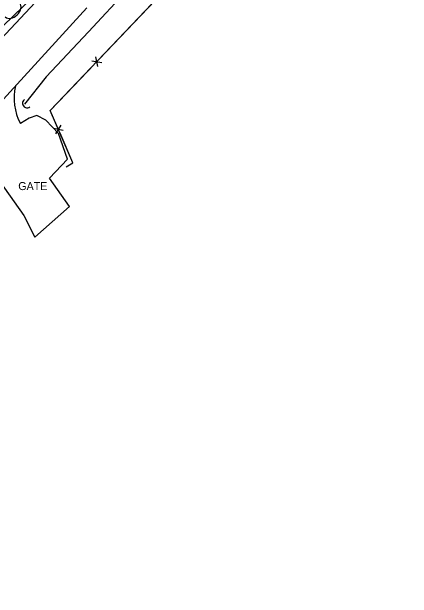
# Model space of a CAD drawing. Extents: x 978516 to 993312, y 1836504 to 1846212.
# Drawn here: x 991834.3 to 992034.4, y 1838414.8 to 1838707.8 of the extents above; entities that cross this region are included whole.
import ezdxf

# ---------------------------------------------------------------- set-up
doc = ezdxf.new("R2010")
doc.units = 0
for name, color, linetype in [('S_CROSS_DRAIN', 7, 'Continuous'), ('S_EDGE_PAVEMENT', 7, 'Continuous'), ('S_FENCE', 7, 'Continuous'), ('S_GATE_ANNOT', 7, 'Continuous'), ('S_PARKING', 7, 'Continuous'), ('S_STREAM', 7, 'Continuous'), ('S_TREE', 7, 'Continuous')]:
    doc.layers.add(name, color=color, linetype=linetype)

msp = doc.modelspace()

# ---------------------------------------------------------------- linework, layer by layer
at = {"layer": 'S_CROSS_DRAIN'}
msp.add_arc((991841.99, 1838662.1), 2.3, 126.4899, 306.8191, dxfattribs=at)
at = {"layer": 'S_EDGE_PAVEMENT'}
for points in [[(991619, 1838423.36), (991630.2, 1838441.16), (991653.43, 1838482.79), (991676.53, 1838520.74), (991692.11, 1838542.33), (991709.31, 1838562.78), (991757.84, 1838618.11), (991795.59, 1838658.21), (991828.79, 1838694.04), (991858.22, 1838725.78)], [(991871.79, 1838709.82), (991824.61, 1838658.29), (991793.15, 1838625.63), (991745.8, 1838573.38), (991714.08, 1838535.8), (991699.23, 1838517.15), (991680.52, 1838488.09), (991668.35, 1838467.09), (991649.18, 1838432.48), (991638.1, 1838414.83)]]:
    msp.add_lwpolyline(points, dxfattribs=at)
at = {"layer": 'S_FENCE'}
for p, q in [((991877.28, 1838680.4), (991876.29, 1838685.3)), ((991874.32, 1838683.22), (991879.26, 1838682.48)), ((991860.04, 1838648.45), (991855.15, 1838649.47)), ((991856.28, 1838646.84), (991858.91, 1838651.09))]:
    msp.add_line(p, q, dxfattribs=at)
for points in [[(991861.4, 1838630.4), (991864.76, 1838632.28), (991853.55, 1838658.39), (991934.9, 1838744.02)], [(991891.94, 1838698.8), (991905.72, 1838713.3)], [(991878.17, 1838684.3), (991891.94, 1838698.8)], [(991861.63, 1838666.9), (991875.41, 1838681.4)], [(991856.81, 1838650.8), (991853.55, 1838658.39), (991861.63, 1838666.9)], [(991861.4, 1838630.4), (991864.76, 1838632.28), (991858.39, 1838647.12)]]:
    msp.add_lwpolyline(points, dxfattribs=at)
at = {"layer": 'S_PARKING'}
msp.add_lwpolyline([(991822.88, 1838630.45), (991840.3, 1838606), (991845.75, 1838595.15), (991863.14, 1838610.43), (991853.21, 1838624.61), (991862.11, 1838634.21), (991857.63, 1838646.95), (991851.24, 1838653.56), (991846.76, 1838655.98), (991842.93, 1838654.7), (991838.6, 1838651.92)], dxfattribs=at)
msp.add_ellipse((991862.41, 1838664.54), major_axis=(4.42, -26.58), ratio=0.999982, start_param=4.316456, end_param=5.035051, dxfattribs=at)
at = {"layer": 'S_STREAM'}
msp.add_lwpolyline([(992034.35, 1838867.71), (991988.82, 1838822.43), (991953.23, 1838784.52), (991912.32, 1838740.5), (991872.6, 1838697.8), (991851.48, 1838675.32), (991840.59, 1838661.56)], dxfattribs=at)
at = {"layer": 'S_TREE'}
msp.add_lwpolyline([(991860.31, 1838730.14), (991768.97, 1838641.99), (991682.77, 1838531.4), (991600.96, 1838449.93)], dxfattribs=at)
msp.add_ellipse((991834.64, 1838708.66), major_axis=(3.57, 3.44), ratio=0.682618, start_param=3.141593, end_param=6.283185, dxfattribs=at)

# ---------------------------------------------------------------- texts
at = {"layer": 'S_GATE_ANNOT'}
msp.add_text('GATE', height=4, dxfattribs=at).set_placement((991837.53, 1838618.71))

doc.saveas('drawing.dxf')
